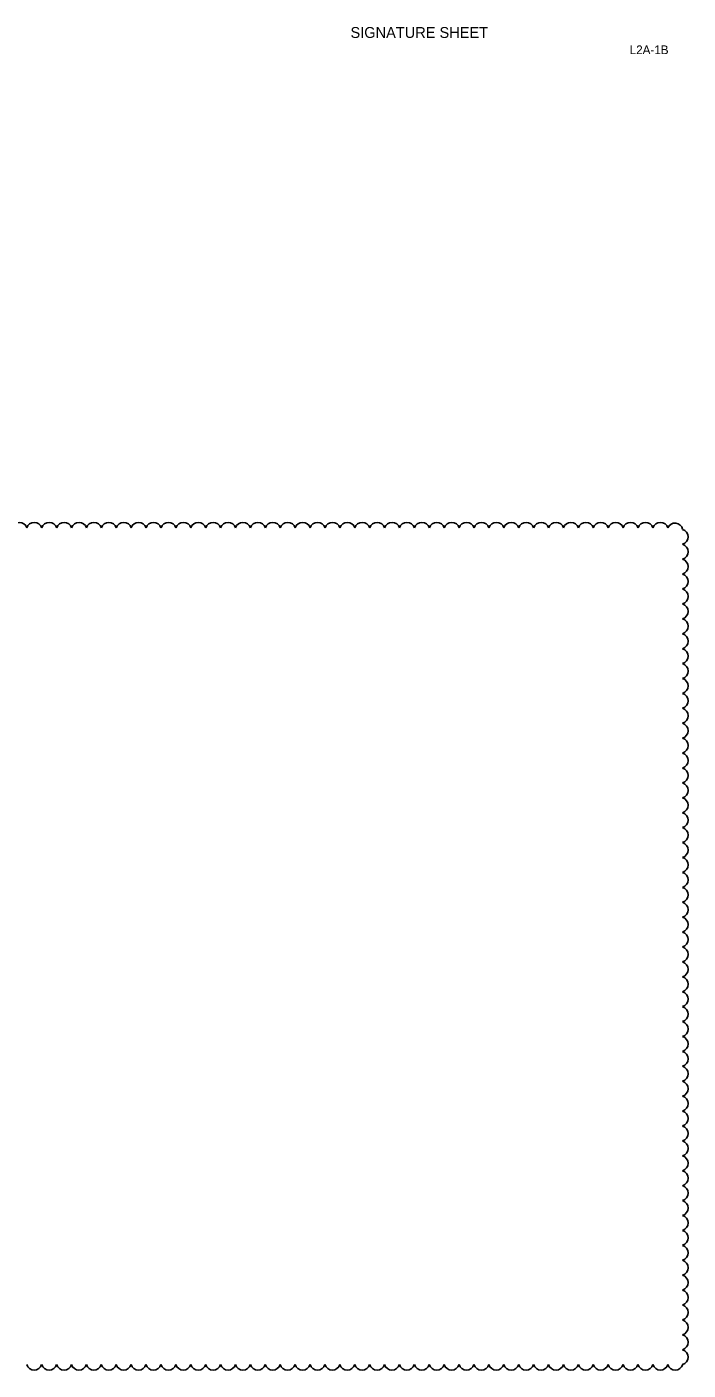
# Model space of a CAD drawing. Extents: x -811 to 10319, y -2309 to 9962.
# Drawn here: x -802.91 to -795.32, y -2229.34 to -2213.93 of the extents above; entities that cross this region are included whole.
import ezdxf

# ---------------------------------------------------------------- set-up
doc = ezdxf.new("R2010")
doc.units = 0
for name, color, linetype in [('PlotBorder_dp', 7, 'Continuous'), ('SheetLines_dp', 7, 'Continuous'), ('TextTitle', 7, 'Continuous')]:
    doc.layers.add(name, color=color, linetype=linetype)

msp = doc.modelspace()

# ---------------------------------------------------------------- linework, layer by layer
at = {"layer": 'TextTitle'}
for centre, radius, start, end in [((-803, -2219.707), 0.0897, 17.5, 162.5), ((-802.829, -2219.707), 0.0897, 17.5, 162.5), ((-802.657, -2219.707), 0.0897, 17.5, 162.5), ((-802.486, -2219.707), 0.0897, 17.5, 162.5), ((-802.315, -2219.707), 0.0897, 17.5, 162.5), ((-802.144, -2219.707), 0.0897, 17.5, 162.5), ((-801.973, -2219.707), 0.0897, 17.5, 162.5), ((-801.802, -2219.707), 0.0897, 17.5, 162.5), ((-801.631, -2219.707), 0.0897, 17.5, 162.5), ((-801.46, -2219.707), 0.0897, 17.5, 162.5), ((-801.288, -2219.707), 0.0897, 17.5, 162.5), ((-801.117, -2219.707), 0.0897, 17.5, 162.5), ((-800.946, -2219.707), 0.0897, 17.5, 162.5), ((-800.775, -2219.707), 0.0897, 17.5, 162.5), ((-800.604, -2219.707), 0.0897, 17.5, 162.5), ((-800.433, -2219.707), 0.0897, 17.5, 162.5), ((-800.262, -2219.707), 0.0897, 17.5, 162.5), ((-800.091, -2219.707), 0.0897, 17.5, 162.5), ((-799.919, -2219.707), 0.0897, 17.5, 162.5), ((-799.748, -2219.707), 0.0897, 17.5, 162.5), ((-799.577, -2219.707), 0.0897, 17.5, 162.5), ((-799.406, -2219.707), 0.0897, 17.5, 162.5), ((-799.235, -2219.707), 0.0897, 17.5, 162.5), ((-799.064, -2219.707), 0.0897, 17.5, 162.5), ((-798.893, -2219.707), 0.0897, 17.5, 162.5), ((-798.722, -2219.707), 0.0897, 17.5, 162.5), ((-798.551, -2219.707), 0.0897, 17.5, 162.5), ((-798.379, -2219.707), 0.0897, 17.5, 162.5), ((-798.208, -2219.707), 0.0897, 17.5, 162.5), ((-798.037, -2219.707), 0.0897, 17.5, 162.5), ((-797.866, -2219.707), 0.0897, 17.5, 162.5), ((-797.695, -2219.707), 0.0897, 17.5, 162.5), ((-797.524, -2219.707), 0.0897, 17.5, 162.5), ((-797.353, -2219.707), 0.0897, 17.5, 162.5), ((-797.182, -2219.707), 0.0897, 17.5, 162.5), ((-797.01, -2219.707), 0.0897, 17.5, 162.5), ((-796.839, -2219.707), 0.0897, 17.5, 162.5), ((-796.668, -2219.707), 0.0897, 17.5, 162.5), ((-796.497, -2219.707), 0.0897, 17.5, 162.5), ((-796.326, -2219.707), 0.0897, 17.5, 162.5), ((-796.155, -2219.707), 0.0897, 17.5, 162.5), ((-795.984, -2219.707), 0.0897, 17.5, 162.5), ((-795.813, -2219.707), 0.0897, 17.5, 162.5), ((-795.641, -2219.707), 0.0897, 17.5, 162.5), ((-795.474, -2219.715), 0.0896, 11.7454, 156.7454), ((-795.413, -2219.783), 0.0897, 287.5, 72.5), ((-795.413, -2219.954), 0.0897, 287.5, 72.5), ((-795.413, -2220.125), 0.0897, 287.5, 72.5), ((-795.413, -2220.296), 0.0897, 287.5, 72.5), ((-795.413, -2220.467), 0.0897, 287.5, 72.5), ((-795.413, -2220.638), 0.0897, 287.5, 72.5), ((-795.413, -2220.809), 0.0897, 287.5, 72.5), ((-795.413, -2220.981), 0.0897, 287.5, 72.5), ((-795.413, -2221.152), 0.0897, 287.5, 72.5), ((-795.413, -2221.323), 0.0897, 287.5, 72.5), ((-795.413, -2221.494), 0.0897, 287.5, 72.5), ((-795.413, -2221.665), 0.0897, 287.5, 72.5), ((-795.413, -2221.836), 0.0897, 287.5, 72.5), ((-795.413, -2222.007), 0.0897, 287.5, 72.5), ((-795.413, -2222.178), 0.0897, 287.5, 72.5), ((-795.413, -2222.35), 0.0897, 287.5, 72.5), ((-795.413, -2222.521), 0.0897, 287.5, 72.5), ((-795.413, -2222.692), 0.0897, 287.5, 72.5), ((-795.413, -2222.863), 0.0897, 287.5, 72.5), ((-795.413, -2223.034), 0.0897, 287.5, 72.5), ((-795.413, -2223.205), 0.0897, 287.5, 72.5), ((-795.413, -2223.376), 0.0897, 287.5, 72.5), ((-795.413, -2223.547), 0.0897, 287.5, 72.5), ((-795.413, -2223.719), 0.0897, 287.5, 72.5), ((-795.413, -2223.89), 0.0897, 287.5, 72.5), ((-795.413, -2224.061), 0.0897, 287.5, 72.5), ((-795.413, -2224.232), 0.0897, 287.5, 72.5), ((-795.413, -2224.403), 0.0897, 287.5, 72.5), ((-795.413, -2224.574), 0.0897, 287.5, 72.5), ((-795.413, -2224.745), 0.0897, 287.5, 72.5), ((-795.413, -2224.916), 0.0897, 287.5, 72.5), ((-795.413, -2225.087), 0.0897, 287.5, 72.5), ((-795.413, -2225.259), 0.0897, 287.5, 72.5), ((-795.413, -2225.43), 0.0897, 287.5, 72.5), ((-795.413, -2225.601), 0.0897, 287.5, 72.5), ((-795.413, -2225.772), 0.0897, 287.5, 72.5), ((-795.413, -2225.943), 0.0897, 287.5, 72.5), ((-795.413, -2226.114), 0.0897, 287.5, 72.5), ((-795.413, -2226.285), 0.0897, 287.5, 72.5), ((-795.413, -2226.456), 0.0897, 287.5, 72.5), ((-795.413, -2226.628), 0.0897, 287.5, 72.5), ((-795.413, -2226.799), 0.0897, 287.5, 72.5), ((-795.413, -2226.97), 0.0897, 287.5, 72.5), ((-795.413, -2227.141), 0.0897, 287.5, 72.5), ((-795.413, -2227.312), 0.0897, 287.5, 72.5), ((-795.413, -2227.483), 0.0897, 287.5, 72.5), ((-795.413, -2227.654), 0.0897, 287.5, 72.5), ((-795.413, -2227.825), 0.0897, 287.5, 72.5), ((-795.413, -2227.997), 0.0897, 287.5, 72.5), ((-795.413, -2228.168), 0.0897, 287.5, 72.5), ((-795.413, -2228.339), 0.0897, 287.5, 72.5), ((-795.413, -2228.51), 0.0897, 287.5, 72.5), ((-795.413, -2228.681), 0.0897, 287.5, 72.5), ((-795.413, -2228.852), 0.0897, 287.5, 72.5), ((-795.413, -2229.023), 0.0897, 287.5, 72.5), ((-795.413, -2229.194), 0.0897, 287.5, 72.5), ((-802.83, -2229.253), 0.0897, 197.5, 342.5), ((-802.658, -2229.253), 0.0897, 197.5, 342.5), ((-802.487, -2229.253), 0.0897, 197.5, 342.5), ((-802.316, -2229.253), 0.0897, 197.5, 342.5), ((-802.145, -2229.253), 0.0897, 197.5, 342.5), ((-801.974, -2229.253), 0.0897, 197.5, 342.5), ((-801.803, -2229.253), 0.0897, 197.5, 342.5), ((-801.632, -2229.253), 0.0897, 197.5, 342.5), ((-801.461, -2229.253), 0.0897, 197.5, 342.5), ((-801.289, -2229.253), 0.0897, 197.5, 342.5), ((-801.118, -2229.253), 0.0897, 197.5, 342.5), ((-800.947, -2229.253), 0.0897, 197.5, 342.5), ((-800.776, -2229.253), 0.0897, 197.5, 342.5), ((-800.605, -2229.253), 0.0897, 197.5, 342.5), ((-800.434, -2229.253), 0.0897, 197.5, 342.5), ((-800.263, -2229.253), 0.0897, 197.5, 342.5), ((-800.092, -2229.253), 0.0897, 197.5, 342.5), ((-799.921, -2229.253), 0.0897, 197.5, 342.5), ((-799.749, -2229.253), 0.0897, 197.5, 342.5), ((-799.578, -2229.253), 0.0897, 197.5, 342.5), ((-799.407, -2229.253), 0.0897, 197.5, 342.5), ((-799.236, -2229.253), 0.0897, 197.5, 342.5), ((-799.065, -2229.253), 0.0897, 197.5, 342.5), ((-798.894, -2229.253), 0.0897, 197.5, 342.5), ((-798.723, -2229.253), 0.0897, 197.5, 342.5), ((-798.552, -2229.253), 0.0897, 197.5, 342.5), ((-798.38, -2229.253), 0.0897, 197.5, 342.5), ((-798.209, -2229.253), 0.0897, 197.5, 342.5), ((-798.038, -2229.253), 0.0897, 197.5, 342.5), ((-797.867, -2229.253), 0.0897, 197.5, 342.5), ((-797.696, -2229.253), 0.0897, 197.5, 342.5), ((-797.525, -2229.253), 0.0897, 197.5, 342.5), ((-797.354, -2229.253), 0.0897, 197.5, 342.5), ((-797.183, -2229.253), 0.0897, 197.5, 342.5), ((-797.011, -2229.253), 0.0897, 197.5, 342.5), ((-796.84, -2229.253), 0.0897, 197.5, 342.5), ((-796.669, -2229.253), 0.0897, 197.5, 342.5), ((-796.498, -2229.253), 0.0897, 197.5, 342.5), ((-796.327, -2229.253), 0.0897, 197.5, 342.5), ((-796.156, -2229.253), 0.0897, 197.5, 342.5), ((-795.985, -2229.253), 0.0897, 197.5, 342.5), ((-795.814, -2229.253), 0.0897, 197.5, 342.5), ((-795.642, -2229.253), 0.0897, 197.5, 342.5), ((-795.471, -2229.253), 0.0897, 197.5, 342.5)]:
    msp.add_arc(centre, radius, start, end, dxfattribs=at)

# ---------------------------------------------------------------- texts
at = {"layer": 'PlotBorder_dp'}
msp.add_text('       SIGNATURE SHEET         ', height=0.125, dxfattribs=at).set_placement((-799.524, -2214.06))
at = {"layer": 'SheetLines_dp'}
msp.add_text('L2A-1B', height=0.1, dxfattribs=at).set_placement((-795.994, -2214.246))

doc.saveas('drawing.dxf')
